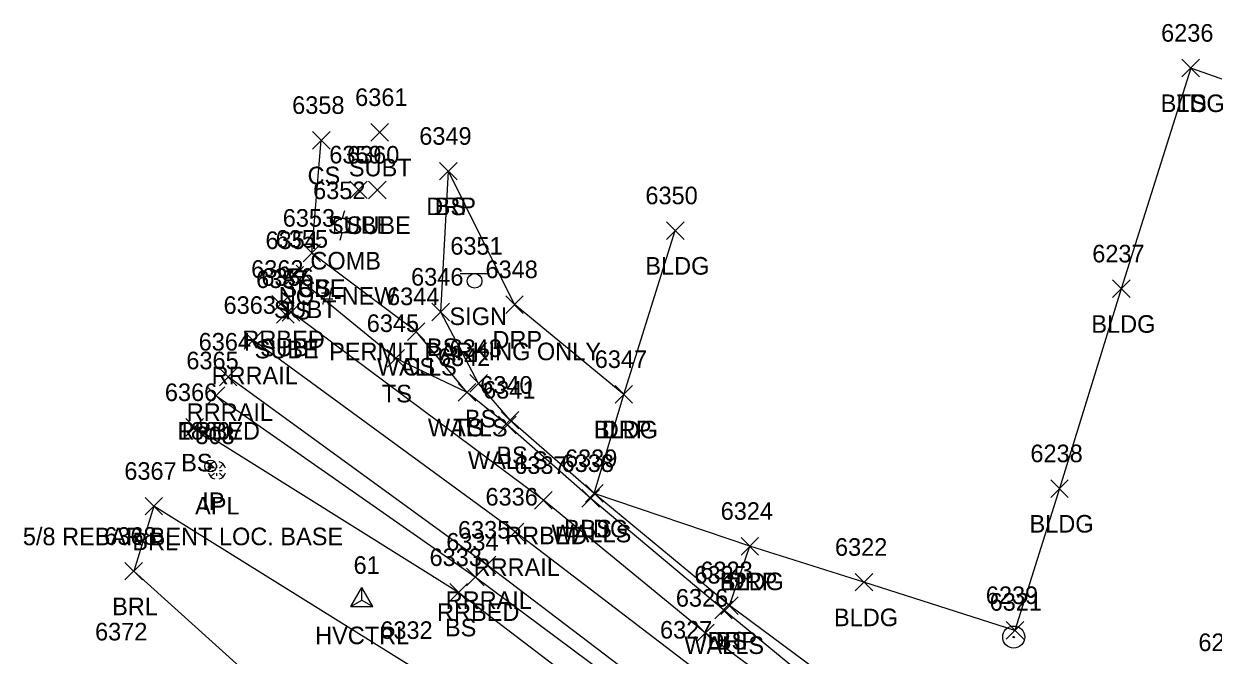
# Model space of a CAD drawing. Extents: x 1618146 to 1620418, y 640749 to 641927.
# Drawn here: x 1619632 to 1619767.2, y 641543.6 to 641615.3 of the extents above; entities that cross this region are included whole.
import ezdxf

# ---------------------------------------------------------------- set-up
doc = ezdxf.new("R2010")
doc.units = 0
for name, color, linetype in [('C_A', 7, 'Continuous'), ('C_I', 7, 'Continuous'), ('CPSM', 7, 'Continuous'), ('Default', 7, 'Continuous'), ('L_A', 7, 'Continuous'), ('L_I', 7, 'Continuous'), ('L_TIC', 7, 'Continuous'), ('LABL', 7, 'Continuous'), ('LBC', 7, 'Continuous'), ('LELB', 7, 'Continuous'), ('LWS', 7, 'Continuous'), ('M_A', 7, 'Continuous'), ('M_C', 7, 'Continuous'), ('M_I', 7, 'Continuous'), ('MPIR', 7, 'Continuous'), ('R_A', 7, 'Continuous'), ('R_I', 7, 'Continuous'), ('R_TIC', 7, 'Continuous'), ('RDP', 7, 'Continuous'), ('RGP', 7, 'Continuous'), ('RR', 7, 'Continuous'), ('RRB', 7, 'Continuous'), ('S_A', 7, 'Continuous'), ('S_C', 7, 'Continuous'), ('S_I', 7, 'Continuous'), ('SSGN', 7, 'Continuous'), ('U_A', 7, 'Continuous'), ('U_C', 7, 'Continuous'), ('U_I', 7, 'Continuous'), ('U_TIC', 7, 'Continuous'), ('UP', 7, 'Continuous')]:
    doc.layers.add(name, color=color, linetype=linetype)

msp = doc.modelspace()

# ---------------------------------------------------------------- linework, layer by layer
at = {"layer": 'CPSM'}
for p, q in [((1619669.2, 641549.09), (1619670.45, 641551.25)), ((1619671.7, 641549.09), (1619670.45, 641551.25)), ((1619670.45, 641549.81), (1619670.45, 641551.25)), ((1619669.2, 641549.09), (1619670.45, 641549.81)), ((1619669.2, 641549.09), (1619671.7, 641549.09)), ((1619670.45, 641549.81), (1619670.45, 641549.81)), ((1619670.45, 641549.81), (1619671.7, 641549.09))]:
    msp.add_line(p, q, dxfattribs=at)
at = {"layer": 'Default'}
for p, q in [((1619653.34, 641565.19), (1619653.69, 641564.84)), ((1619653.98, 641564.86), (1619653.98, 641565.16)), ((1619654.26, 641564.84), (1619654.61, 641565.19)), ((1619653.34, 641563.92), (1619653.69, 641564.27)), ((1619653.38, 641564.56), (1619653.68, 641564.56)), ((1619653.98, 641563.96), (1619653.98, 641564.26)), ((1619654.26, 641564.27), (1619654.61, 641563.92)), ((1619654.27, 641564.56), (1619654.58, 641564.56))]:
    msp.add_line(p, q, dxfattribs=at)
for start, end in [(105, 165), (15, 75), (195, 255), (285, 345)]:
    msp.add_arc((1619653.98, 641564.56), 1, start, end, dxfattribs=at)
at = {"layer": 'L_TIC'}
for points in [[(1619763.68, 641609.3), (1619765.68, 641611.3)], [(1619765.68, 641609.3), (1619763.68, 641611.3)], [(1619763.68, 641609.3), (1619765.68, 641611.3)], [(1619765.68, 641609.3), (1619763.68, 641611.3)], [(1619664.84, 641601.09), (1619666.84, 641603.09)], [(1619666.84, 641601.09), (1619664.84, 641603.09)], [(1619679.29, 641597.58), (1619681.29, 641599.58)], [(1619681.29, 641597.58), (1619679.29, 641599.58)], [(1619705.08, 641590.82), (1619707.08, 641592.82)], [(1619707.08, 641590.82), (1619705.08, 641592.82)], [(1619663.77, 641588.27), (1619665.77, 641590.27)], [(1619665.77, 641588.27), (1619663.77, 641590.27)], [(1619661.81, 641585.73), (1619663.81, 641587.73)], [(1619663.81, 641585.73), (1619661.81, 641587.73)], [(1619755.79, 641584.21), (1619757.79, 641586.21)], [(1619757.79, 641584.21), (1619755.79, 641586.21)], [(1619678.42, 641581.57), (1619680.42, 641583.57)], [(1619680.42, 641581.57), (1619678.42, 641583.57)], [(1619675.63, 641579.35), (1619677.63, 641581.35)], [(1619677.63, 641579.35), (1619675.63, 641581.35)], [(1619675.63, 641579.35), (1619677.63, 641581.35)], [(1619677.63, 641579.35), (1619675.63, 641581.35)], [(1619673.32, 641576.3), (1619675.32, 641578.3)], [(1619675.32, 641576.3), (1619673.32, 641578.3)], [(1619682.73, 641573.46), (1619684.73, 641575.46)], [(1619684.73, 641573.46), (1619682.73, 641575.46)], [(1619681.41, 641572.43), (1619683.41, 641574.43)], [(1619683.41, 641572.43), (1619681.41, 641574.43)], [(1619681.41, 641572.43), (1619683.41, 641574.43)], [(1619683.41, 641572.43), (1619681.41, 641574.43)], [(1619699.24, 641572.21), (1619701.24, 641574.21)], [(1619701.24, 641572.21), (1619699.24, 641574.21)], [(1619650.46, 641568.45), (1619652.46, 641570.45)], [(1619652.46, 641568.45), (1619650.46, 641570.45)], [(1619685.98, 641568.73), (1619687.98, 641570.73)], [(1619687.98, 641568.73), (1619685.98, 641570.73)], [(1619686.3, 641569.28), (1619688.3, 641571.28)], [(1619688.3, 641569.28), (1619686.3, 641571.28)], [(1619695.47, 641560.39), (1619697.47, 641562.39)], [(1619697.47, 641560.39), (1619695.47, 641562.39)], [(1619695.87, 641560.95), (1619697.87, 641562.95)], [(1619697.87, 641560.95), (1619695.87, 641562.95)], [(1619695.87, 641560.95), (1619697.87, 641562.95)], [(1619697.87, 641560.95), (1619695.87, 641562.95)], [(1619748.77, 641561.5), (1619750.77, 641563.5)], [(1619750.77, 641561.5), (1619748.77, 641563.5)], [(1619645.8, 641559.5), (1619647.8, 641561.5)], [(1619647.8, 641559.5), (1619645.8, 641561.5)], [(1619713.56, 641554.95), (1619715.56, 641556.95)], [(1619715.56, 641554.95), (1619713.56, 641556.95)], [(1619643.52, 641552.11), (1619645.52, 641554.11)], [(1619645.52, 641552.11), (1619643.52, 641554.11)], [(1619726.54, 641550.86), (1619728.54, 641552.86)], [(1619728.54, 641550.86), (1619726.54, 641552.86)], [(1619680.45, 641549.7), (1619682.45, 641551.7)], [(1619682.45, 641549.7), (1619680.45, 641551.7)], [(1619711.25, 641548.2), (1619713.25, 641550.2)], [(1619713.25, 641548.2), (1619711.25, 641550.2)], [(1619710.57, 641547.7), (1619712.57, 641549.7)], [(1619712.57, 641547.7), (1619710.57, 641549.7)], [(1619743.7, 641545.38), (1619745.7, 641547.38)], [(1619745.7, 641545.38), (1619743.7, 641547.38)]]:
    msp.add_lwpolyline(points, dxfattribs=at)
at = {"layer": 'LABL'}
msp.add_lwpolyline([(1619897.21, 641367.93), (1619884.43, 641382.4), (1619853.25, 641407.41), (1619812.86, 641441.7), (1619772.36, 641467.89), (1619746.52, 641491.7), (1619723.5, 641512.01), (1619698.77, 641530.96), (1619675.85, 641542.41), (1619646.8, 641560.5), (1619644.52, 641553.11), (1619671.66, 641528.64)], dxfattribs=at)
at = {"layer": 'LBC'}
msp.add_lwpolyline([(1619764.68, 641610.3), (1619756.79, 641585.21), (1619749.77, 641562.5), (1619744.7, 641546.38), (1619727.54, 641551.86), (1619714.56, 641555.95), (1619696.87, 641561.95), (1619700.24, 641573.21), (1619706.08, 641591.82)], dxfattribs=at)
at = {"layer": 'LELB'}
for points in [[(1619959.82, 641357.09), (1619968.82, 641370.56), (1619944.08, 641390.01), (1619910.61, 641416.55), (1619871.74, 641447.47), (1619859.45, 641460.52), (1619829.4, 641492.07), (1619805.61, 641511.37), (1619797.78, 641518.22), (1619768.87, 641541.03), (1619773.26, 641565.04), (1619780.17, 641589.77), (1619783.72, 641603.58), (1619764.68, 641610.3)], [(1619676.63, 641580.35), (1619664.77, 641589.27), (1619665.84, 641602.09)], [(1619712.25, 641549.2), (1619696.87, 641561.95), (1619687.3, 641570.28), (1619683.73, 641574.46), (1619679.42, 641582.57), (1619680.29, 641598.58)], [(1619682.41, 641573.43), (1619674.32, 641577.3), (1619662.81, 641586.73)], [(1619751.61, 641498.17), (1619727.29, 641517.05), (1619701.89, 641535.08), (1619681.45, 641550.7), (1619651.46, 641569.45)]]:
    msp.add_lwpolyline(points, dxfattribs=at)
at = {"layer": 'LWS'}
msp.add_lwpolyline([(1619735.21, 641529.23), (1619711.57, 641548.7), (1619696.47, 641561.39), (1619686.98, 641569.73), (1619682.41, 641573.43), (1619676.63, 641580.35)], dxfattribs=at)
at = {"layer": 'MPIR'}
msp.add_lwpolyline([(1619653.25, 641565.39), (1619652.96, 641564.89), (1619653.54, 641564.89)], close=True, dxfattribs=at)
msp.add_circle((1619653.25, 641565.06), 0.667, dxfattribs=at)
at = {"layer": 'R_TIC'}
for points in [[(1619679.29, 641597.58), (1619681.29, 641599.58)], [(1619681.29, 641597.58), (1619679.29, 641599.58)], [(1619660.22, 641582.46), (1619662.22, 641584.46)], [(1619662.22, 641582.46), (1619660.22, 641584.46)], [(1619686.81, 641582.42), (1619688.81, 641584.42)], [(1619688.81, 641582.42), (1619686.81, 641584.42)], [(1619657.08, 641578.36), (1619659.08, 641580.36)], [(1619659.08, 641578.36), (1619657.08, 641580.36)], [(1619654.25, 641574.19), (1619656.25, 641576.19)], [(1619656.25, 641574.19), (1619654.25, 641576.19)], [(1619652.86, 641572.06), (1619654.86, 641574.06)], [(1619654.86, 641572.06), (1619652.86, 641574.06)], [(1619699.24, 641572.21), (1619701.24, 641574.21)], [(1619701.24, 641572.21), (1619699.24, 641574.21)], [(1619690.09, 641560.17), (1619692.09, 641562.17)], [(1619692.09, 641560.17), (1619690.09, 641562.17)], [(1619686.87, 641556.57), (1619688.87, 641558.57)], [(1619688.87, 641556.57), (1619686.87, 641558.57)], [(1619713.56, 641554.95), (1619715.56, 641556.95)], [(1619715.56, 641554.95), (1619713.56, 641556.95)], [(1619683.69, 641552.81), (1619685.69, 641554.81)], [(1619685.69, 641552.81), (1619683.69, 641554.81)], [(1619682.35, 641551.45), (1619684.35, 641553.45)], [(1619684.35, 641551.45), (1619682.35, 641553.45)], [(1619711.25, 641548.2), (1619713.25, 641550.2)], [(1619713.25, 641548.2), (1619711.25, 641550.2)], [(1619708.51, 641545.08), (1619710.51, 641547.08)], [(1619710.51, 641545.08), (1619708.51, 641547.08)]]:
    msp.add_lwpolyline(points, dxfattribs=at)
at = {"layer": 'RDP'}
for points in [[(1619700.24, 641573.21), (1619687.81, 641583.42), (1619680.29, 641598.58)], [(1620046.29, 641425.2), (1620030.82, 641393.12), (1620022.2, 641371.36), (1620020.19, 641367.26), (1619996.2, 641331.35), (1619976.43, 641344.3), (1619959.82, 641357.09), (1619936.33, 641374.65), (1619891.26, 641410.4), (1619869.71, 641427.21), (1619819.71, 641475.11), (1619778.81, 641510.61), (1619747.43, 641531.14), (1619747.1, 641530.5), (1619739.15, 641529.24), (1619712.25, 641549.2), (1619714.56, 641555.95)]]:
    msp.add_lwpolyline(points, dxfattribs=at)
at = {"layer": 'RGP'}
msp.add_line((1619744.56, 641545.62), (1619744.56, 641545.62), dxfattribs=at)
for radius in [1.25, 0.0833]:
    msp.add_circle((1619744.56, 641545.62), radius, dxfattribs=at)
at = {"layer": 'RR'}
for points in [[(1619890.89, 641393.62), (1619862.55, 641416.89), (1619821.51, 641450.86), (1619785.3, 641481.06), (1619755.67, 641504.7), (1619731.68, 641523.97), (1619707.65, 641542.45), (1619687.87, 641557.57), (1619658.08, 641579.36)], [(1619888.22, 641389.6), (1619859.16, 641413.43), (1619820.99, 641444.88), (1619782.25, 641477.02), (1619752.76, 641500.88), (1619728.78, 641520.01), (1619704.99, 641538.38), (1619684.69, 641553.81), (1619655.25, 641575.19)]]:
    msp.add_lwpolyline(points, dxfattribs=at)
at = {"layer": 'RRB'}
for points in [[(1619986.51, 641321.42), (1619974.99, 641328.72), (1619954.79, 641347.39), (1619947.15, 641351.81), (1619929.64, 641366.47), (1619892.95, 641395.78), (1619865.64, 641419.74), (1619823.44, 641453.76), (1619786.96, 641483.75), (1619757.14, 641507.97), (1619741.95, 641521.56), (1619734, 641527.8), (1619709.51, 641546.08), (1619691.09, 641561.17), (1619661.22, 641583.46)], [(1619977.87, 641310.92), (1619966.34, 641319.18), (1619955.14, 641328.07), (1619947.13, 641336.24), (1619940.39, 641342.13), (1619921.41, 641357.17), (1619886.68, 641385.78), (1619856.81, 641410.87), (1619815.24, 641443.99), (1619779.42, 641474.24), (1619751.61, 641498.17), (1619728.14, 641518.29), (1619703.69, 641537.28), (1619683.35, 641552.45), (1619653.86, 641573.06)]]:
    msp.add_lwpolyline(points, dxfattribs=at)
at = {"layer": 'SSGN'}
for p, q in [((1619681.63, 641586.94), (1619684.96, 641586.94)), ((1619683.27, 641586.11), (1619683.27, 641586.11))]:
    msp.add_line(p, q, dxfattribs=at)
msp.add_circle((1619683.27, 641586.11), 0.833, dxfattribs=at)
at = {"layer": 'U_TIC'}
for points in [[(1619671.48, 641601.99), (1619673.48, 641603.99)], [(1619673.48, 641601.99), (1619671.48, 641603.99)], [(1619669.07, 641595.46), (1619671.07, 641597.46)], [(1619671.07, 641595.46), (1619669.07, 641597.46)], [(1619671.2, 641595.44), (1619673.2, 641597.44)], [(1619673.2, 641595.44), (1619671.2, 641597.44)], [(1619663.77, 641588.27), (1619665.77, 641590.27)], [(1619665.77, 641588.27), (1619663.77, 641590.27)], [(1619662.97, 641585.88), (1619664.97, 641587.88)], [(1619664.97, 641585.88), (1619662.97, 641587.88)], [(1619660.74, 641581.3), (1619662.74, 641583.3)], [(1619662.74, 641581.3), (1619660.74, 641583.3)], [(1619661.39, 641581.54), (1619663.39, 641583.54)], [(1619663.39, 641581.54), (1619661.39, 641583.54)]]:
    msp.add_lwpolyline(points, dxfattribs=at)
at = {"layer": 'UP'}
for p, q in [((1619668.47, 641594.07), (1619668.22, 641593.23)), ((1619667.38, 641591.57), (1619667.38, 641593.23)), ((1619667.38, 641593.23), (1619669.05, 641593.23)), ((1619668.22, 641592.4), (1619668.22, 641592.4)), ((1619669.05, 641593.23), (1619669.05, 641591.57)), ((1619669.05, 641591.57), (1619667.38, 641591.57)), ((1619667.97, 641590.73), (1619668.22, 641591.57))]:
    msp.add_line(p, q, dxfattribs=at)
msp.add_circle((1619668.22, 641592.4), 0.833, dxfattribs=at)

# ---------------------------------------------------------------- texts
at = {"layer": 'C_A'}
msp.add_text('HVCTRL', height=2, dxfattribs=at).set_placement((1619665.14, 641544.81))
at = {"layer": 'C_I'}
msp.add_text('61', height=2, dxfattribs=at).set_placement((1619669.51, 641552.81))
at = {"layer": 'L_A'}
for s, p in [('BLDG', (1619761.27, 641605.3)), ('TS', (1619763.09, 641605.3)), ('CS', (1619664.28, 641597.09)), ('BS', (1619678.73, 641593.58)), ('BLDG', (1619702.68, 641586.82)), ('CS', (1619663.21, 641584.27)), ('TS', (1619661.22, 641581.73)), ('BLDG', (1619753.39, 641580.21)), ('BS', (1619677.86, 641577.57)), ('WALLS', (1619672.17, 641575.35)), ('CS', (1619675.07, 641575.35)), ('TS', (1619672.73, 641572.3)), ('WALLS', (1619677.96, 641568.43)), ('TS', (1619680.82, 641568.43)), ('BS', (1619682.17, 641569.46)), ('BLDG', (1619696.83, 641568.21)), ('BS', (1619649.91, 641564.45)), ('WALLS', (1619682.52, 641564.73)), ('BS', (1619685.74, 641565.28)), ('WALLS', (1619692.02, 641556.39)), ('BLDG', (1619693.46, 641556.95)), ('BS', (1619695.31, 641556.95)), ('BLDG', (1619746.36, 641557.5)), ('BRL', (1619644.35, 641555.5)), ('BLDG', (1619711.15, 641550.95)), ('BRL', (1619642.06, 641548.11)), ('BLDG', (1619724.13, 641546.86)), ('BS', (1619679.9, 641545.7)), ('BS', (1619710.69, 641544.2)), ('WALLS', (1619707.11, 641543.7))]:
    msp.add_text(s, height=2, dxfattribs=at).set_placement(p)
at = {"layer": 'L_I'}
for s, p in [('6236', (1619761.32, 641613.3)), ('6236', (1619761.32, 641613.3)), ('6358', (1619662.53, 641605.09)), ('6349', (1619676.98, 641601.58)), ('6350', (1619702.69, 641594.82)), ('6353', (1619661.46, 641592.27)), ('6354', (1619659.5, 641589.73)), ('6237', (1619753.49, 641588.21)), ('6346', (1619676.05, 641585.57)), ('6344', (1619673.32, 641583.35)), ('6344', (1619673.32, 641583.35)), ('6345', (1619671.01, 641580.3)), ('6343', (1619680.42, 641577.46)), ('6342', (1619679.11, 641576.43)), ('6342', (1619679.11, 641576.43)), ('6347', (1619696.93, 641576.21)), ('6366', (1619648.06, 641572.45)), ('6340', (1619683.91, 641573.28)), ('6341', (1619684.24, 641572.73)), ('6338', (1619693.16, 641564.39)), ('6339', (1619693.55, 641564.95)), ('6339', (1619693.55, 641564.95)), ('6238', (1619746.46, 641565.5)), ('6367', (1619643.45, 641563.5)), ('6324', (1619711.25, 641558.95)), ('6368', (1619641.17, 641556.11)), ('6322', (1619724.24, 641554.86)), ('6333', (1619678.15, 641553.7)), ('6323', (1619708.94, 641552.2)), ('6325', (1619708.26, 641551.7)), ('6239', (1619741.39, 641549.38)), ('6332', (1619672.55, 641545.41)), ('6232', (1619765.56, 641544.03))]:
    msp.add_text(s, height=2, dxfattribs=at).set_placement(p)
at = {"layer": 'M_A'}
for s, p in [('APL', (1619651.49, 641559.56)), ('IP', (1619652.3, 641560.06))]:
    msp.add_text(s, height=2, dxfattribs=at).set_placement(p)
at = {"layer": 'M_C'}
msp.add_text('5/8 REBAR BENT LOC. BASE', height=2, dxfattribs=at).set_placement((1619631.91, 641556.06))
at = {"layer": 'M_I'}
for s, p in [('18607', (1619649.53, 641568.06)), ('303', (1619651.53, 641567.56))]:
    msp.add_text(s, height=2, dxfattribs=at).set_placement(p)
at = {"layer": 'R_A'}
for s, p in [('DRP', (1619677.78, 641593.58)), ('RRBED', (1619656.87, 641578.46)), ('DRP', (1619685.3, 641578.42)), ('RRRAIL', (1619653.37, 641574.36)), ('RRRAIL', (1619650.54, 641570.19)), ('RRBED', (1619649.5, 641568.06)), ('DRP', (1619697.73, 641568.21)), ('RRBED', (1619686.74, 641556.17)), ('RRRAIL', (1619683.16, 641552.57)), ('DRP', (1619712.05, 641550.95)), ('RRRAIL', (1619679.98, 641548.81)), ('RRBED', (1619679, 641547.45)), ('DRP', (1619709.74, 641544.2))]:
    msp.add_text(s, height=2, dxfattribs=at).set_placement(p)
at = {"layer": 'R_I'}
for s, p in [('6349', (1619676.98, 641601.58)), ('6362', (1619657.87, 641586.46)), ('6348', (1619684.51, 641586.42)), ('6363', (1619654.73, 641582.36)), ('6364', (1619651.9, 641578.19)), ('6365', (1619650.5, 641576.06)), ('6347', (1619696.93, 641576.21)), ('6337', (1619687.78, 641564.17)), ('6336', (1619684.51, 641560.57)), ('6324', (1619711.25, 641558.95)), ('6335', (1619681.38, 641556.81)), ('6334', (1619680.05, 641555.45)), ('6323', (1619708.94, 641552.2)), ('6326', (1619706.15, 641549.08)), ('6321', (1619741.82, 641548.62)), ('6327', (1619704.35, 641545.45)), ('6372', (1619640.12, 641545.24))]:
    msp.add_text(s, height=2, dxfattribs=at).set_placement(p)
at = {"layer": 'S_A'}
msp.add_text('SIGN', height=2, dxfattribs=at).set_placement((1619680.41, 641581.09))
at = {"layer": 'S_C'}
msp.add_text('PERMIT PARKING ONLY', height=2, dxfattribs=at).set_placement((1619666.73, 641577.09))
at = {"layer": 'S_I'}
msp.add_text('6351', height=2, dxfattribs=at).set_placement((1619680.51, 641589.09))
at = {"layer": 'U_A'}
for s, p in [('SUBT', (1619668.98, 641597.99)), ('SUBE', (1619666.6, 641591.46)), ('SUBE', (1619668.73, 641591.44)), ('COMB', (1619664.6, 641587.4)), ('SUBE', (1619661.3, 641584.27)), ('SUBT', (1619660.46, 641581.88)), ('SUBE', (1619658.27, 641577.3)), ('SUBT', (1619658.89, 641577.54))]:
    msp.add_text(s, height=2, dxfattribs=at).set_placement(p)
at = {"layer": 'U_C'}
msp.add_text('NO #-NEW', height=2, dxfattribs=at).set_placement((1619661.02, 641583.4))
at = {"layer": 'U_I'}
for s, p in [('6361', (1619669.69, 641605.99)), ('6359', (1619666.75, 641599.46)), ('6360', (1619668.76, 641599.44)), ('6352', (1619664.91, 641595.4)), ('6353', (1619661.46, 641592.27)), ('6355', (1619660.66, 641589.88)), ('6357', (1619658.43, 641585.3)), ('6356', (1619659.03, 641585.54))]:
    msp.add_text(s, height=2, dxfattribs=at).set_placement(p)

doc.saveas('drawing.dxf')
